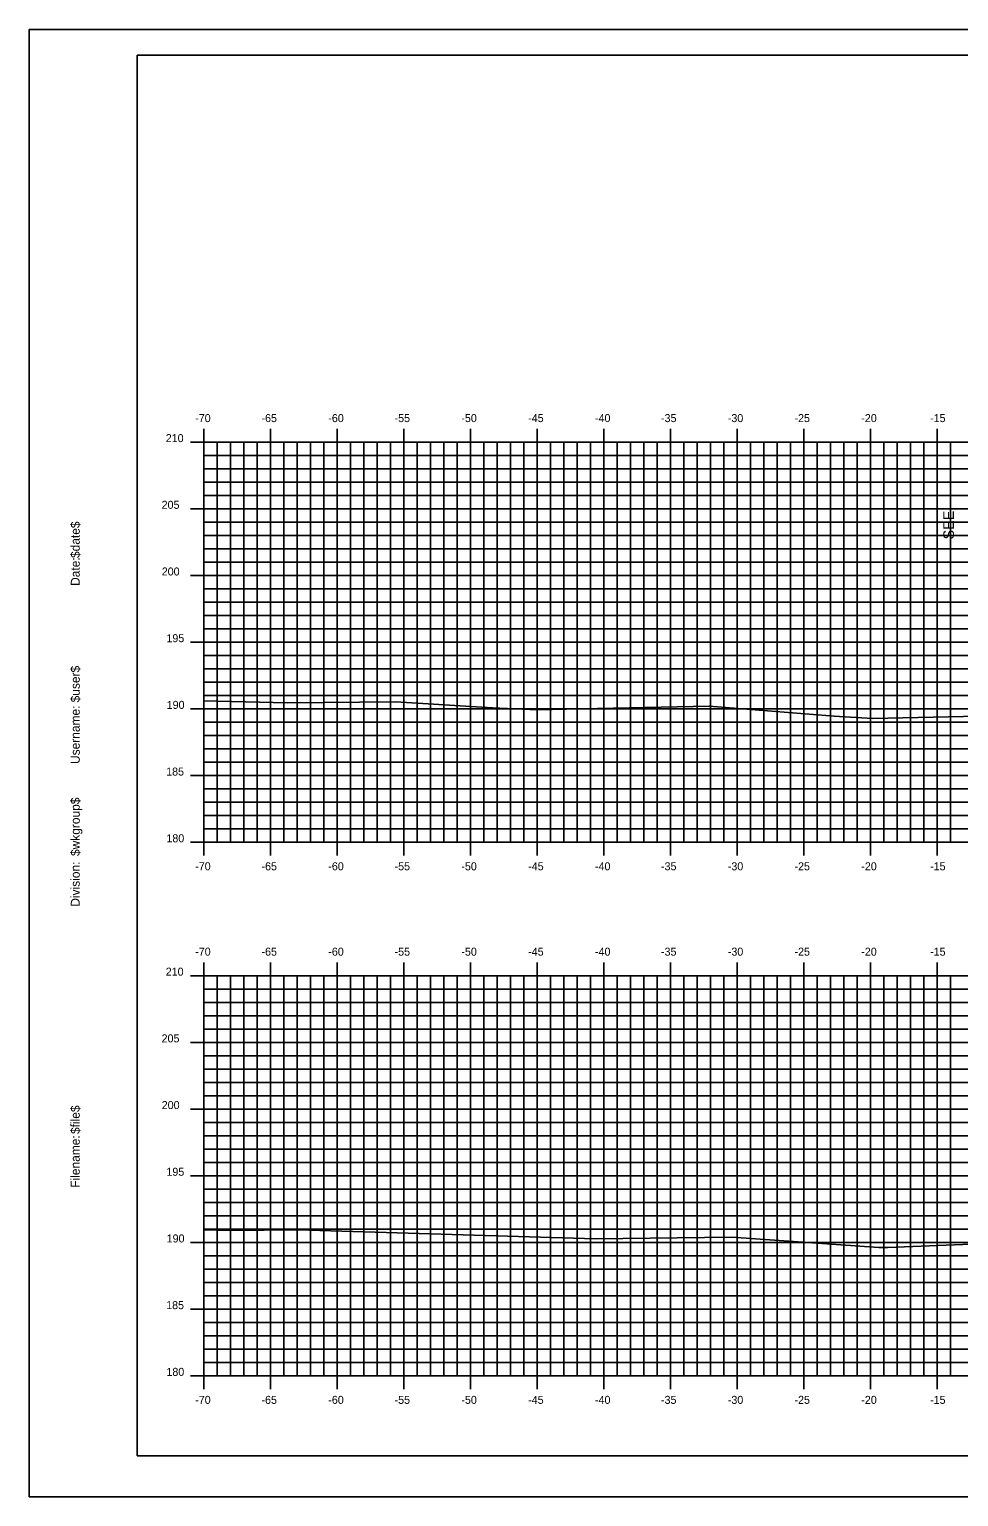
# Model space of a CAD drawing. Extents: x 1723296 to 1723468, y 459560 to 459670.
# Drawn here: x 1723296.1 to 1723365.8, y 459559.6 to 459669.6 of the extents above; entities that cross this region are included whole.
import ezdxf

# ---------------------------------------------------------------- set-up
doc = ezdxf.new("R2010")
doc.units = 0
for name, color, linetype in [('ANNOTATION', 7, 'Continuous'), ('BORDER', 7, 'Continuous'), ('H_V ANNOTATION', 7, 'Continuous'), ('MAJOR', 7, 'Continuous'), ('MINOR', 7, 'Continuous'), ('PLOT BOUNDARY', 7, 'Continuous'), ('S_Roadway_Centerline', 7, 'Continuous')]:
    doc.layers.add(name, color=color, linetype=linetype)

msp = doc.modelspace()

# ---------------------------------------------------------------- linework, layer by layer
at = {"layer": 'BORDER'}
msp.add_lwpolyline([(1723304.2, 459562.61), (1723464.2, 459562.61), (1723464.2, 459667.61), (1723304.2, 459667.61)], close=True, dxfattribs=at)
at = {"layer": 'MAJOR'}
for p, q in [((1723309.2, 459639.61), (1723309.2, 459638.61)), ((1723314.2, 459639.61), (1723314.2, 459638.61)), ((1723319.2, 459639.61), (1723319.2, 459638.61)), ((1723324.2, 459639.61), (1723324.2, 459638.61)), ((1723329.2, 459639.61), (1723329.2, 459638.61)), ((1723334.2, 459639.61), (1723334.2, 459638.61)), ((1723339.2, 459639.61), (1723339.2, 459638.61)), ((1723344.2, 459639.61), (1723344.2, 459638.61)), ((1723349.2, 459639.61), (1723349.2, 459638.61)), ((1723354.2, 459639.61), (1723354.2, 459638.61)), ((1723359.2, 459639.61), (1723359.2, 459638.61)), ((1723364.2, 459639.61), (1723364.2, 459638.61)), ((1723308.2, 459638.61), (1723309.2, 459638.61)), ((1723309.2, 459638.61), (1723449.2, 459638.61)), ((1723309.2, 459608.61), (1723309.2, 459638.61)), ((1723309.2, 459608.61), (1723309.2, 459638.61)), ((1723309.2, 459638.61), (1723449.2, 459638.61)), ((1723314.2, 459608.61), (1723314.2, 459638.61)), ((1723319.2, 459608.61), (1723319.2, 459638.61)), ((1723324.2, 459608.61), (1723324.2, 459638.61)), ((1723329.2, 459608.61), (1723329.2, 459638.61)), ((1723334.2, 459608.61), (1723334.2, 459638.61)), ((1723339.2, 459608.61), (1723339.2, 459638.61)), ((1723344.2, 459608.61), (1723344.2, 459638.61)), ((1723349.2, 459608.61), (1723349.2, 459638.61)), ((1723354.2, 459608.61), (1723354.2, 459638.61)), ((1723359.2, 459608.61), (1723359.2, 459638.61)), ((1723364.2, 459608.61), (1723364.2, 459638.61)), ((1723308.2, 459633.61), (1723309.2, 459633.61)), ((1723309.2, 459633.61), (1723449.2, 459633.61)), ((1723308.2, 459628.61), (1723309.2, 459628.61)), ((1723309.2, 459628.61), (1723449.2, 459628.61)), ((1723308.2, 459623.61), (1723309.2, 459623.61)), ((1723309.2, 459623.61), (1723449.2, 459623.61)), ((1723308.2, 459618.61), (1723309.2, 459618.61)), ((1723309.2, 459618.61), (1723449.2, 459618.61)), ((1723308.2, 459613.61), (1723309.2, 459613.61)), ((1723309.2, 459613.61), (1723449.2, 459613.61)), ((1723308.2, 459608.61), (1723309.2, 459608.61)), ((1723309.2, 459608.61), (1723449.2, 459608.61)), ((1723309.2, 459608.61), (1723449.2, 459608.61)), ((1723309.2, 459607.61), (1723309.2, 459608.61)), ((1723314.2, 459607.61), (1723314.2, 459608.61)), ((1723319.2, 459607.61), (1723319.2, 459608.61)), ((1723324.2, 459607.61), (1723324.2, 459608.61)), ((1723329.2, 459607.61), (1723329.2, 459608.61)), ((1723334.2, 459607.61), (1723334.2, 459608.61)), ((1723339.2, 459607.61), (1723339.2, 459608.61)), ((1723344.2, 459607.61), (1723344.2, 459608.61)), ((1723349.2, 459607.61), (1723349.2, 459608.61)), ((1723354.2, 459607.61), (1723354.2, 459608.61)), ((1723359.2, 459607.61), (1723359.2, 459608.61)), ((1723364.2, 459607.61), (1723364.2, 459608.61)), ((1723309.2, 459599.61), (1723309.2, 459598.61)), ((1723314.2, 459599.61), (1723314.2, 459598.61)), ((1723319.2, 459599.61), (1723319.2, 459598.61)), ((1723324.2, 459599.61), (1723324.2, 459598.61)), ((1723329.2, 459599.61), (1723329.2, 459598.61)), ((1723334.2, 459599.61), (1723334.2, 459598.61)), ((1723339.2, 459599.61), (1723339.2, 459598.61)), ((1723344.2, 459599.61), (1723344.2, 459598.61)), ((1723349.2, 459599.61), (1723349.2, 459598.61)), ((1723354.2, 459599.61), (1723354.2, 459598.61)), ((1723359.2, 459599.61), (1723359.2, 459598.61)), ((1723364.2, 459599.61), (1723364.2, 459598.61)), ((1723308.2, 459598.61), (1723309.2, 459598.61)), ((1723309.2, 459598.61), (1723449.2, 459598.61)), ((1723309.2, 459568.61), (1723309.2, 459598.61)), ((1723309.2, 459568.61), (1723309.2, 459598.61)), ((1723309.2, 459598.61), (1723449.2, 459598.61)), ((1723314.2, 459568.61), (1723314.2, 459598.61)), ((1723319.2, 459568.61), (1723319.2, 459598.61)), ((1723324.2, 459568.61), (1723324.2, 459598.61)), ((1723329.2, 459568.61), (1723329.2, 459598.61)), ((1723334.2, 459568.61), (1723334.2, 459598.61)), ((1723339.2, 459568.61), (1723339.2, 459598.61)), ((1723344.2, 459568.61), (1723344.2, 459598.61)), ((1723349.2, 459568.61), (1723349.2, 459598.61)), ((1723354.2, 459568.61), (1723354.2, 459598.61)), ((1723359.2, 459568.61), (1723359.2, 459598.61)), ((1723364.2, 459568.61), (1723364.2, 459598.61)), ((1723308.2, 459593.61), (1723309.2, 459593.61)), ((1723309.2, 459593.61), (1723449.2, 459593.61)), ((1723308.2, 459588.61), (1723309.2, 459588.61)), ((1723309.2, 459588.61), (1723449.2, 459588.61)), ((1723308.2, 459583.61), (1723309.2, 459583.61)), ((1723309.2, 459583.61), (1723449.2, 459583.61)), ((1723308.2, 459578.61), (1723309.2, 459578.61)), ((1723309.2, 459578.61), (1723449.2, 459578.61)), ((1723308.2, 459573.61), (1723309.2, 459573.61)), ((1723309.2, 459573.61), (1723449.2, 459573.61)), ((1723308.2, 459568.61), (1723309.2, 459568.61)), ((1723309.2, 459568.61), (1723449.2, 459568.61)), ((1723309.2, 459568.61), (1723449.2, 459568.61)), ((1723309.2, 459567.61), (1723309.2, 459568.61)), ((1723314.2, 459567.61), (1723314.2, 459568.61)), ((1723319.2, 459567.61), (1723319.2, 459568.61)), ((1723324.2, 459567.61), (1723324.2, 459568.61)), ((1723329.2, 459567.61), (1723329.2, 459568.61)), ((1723334.2, 459567.61), (1723334.2, 459568.61)), ((1723339.2, 459567.61), (1723339.2, 459568.61)), ((1723344.2, 459567.61), (1723344.2, 459568.61)), ((1723349.2, 459567.61), (1723349.2, 459568.61)), ((1723354.2, 459567.61), (1723354.2, 459568.61)), ((1723359.2, 459567.61), (1723359.2, 459568.61)), ((1723364.2, 459567.61), (1723364.2, 459568.61))]:
    msp.add_line(p, q, dxfattribs=at)
at = {"layer": 'MINOR'}
for p, q in [((1723310.2, 459608.61), (1723310.2, 459638.61)), ((1723311.2, 459608.61), (1723311.2, 459638.61)), ((1723312.2, 459608.61), (1723312.2, 459638.61)), ((1723313.2, 459608.61), (1723313.2, 459638.61)), ((1723315.2, 459608.61), (1723315.2, 459638.61)), ((1723316.2, 459608.61), (1723316.2, 459638.61)), ((1723317.2, 459608.61), (1723317.2, 459638.61)), ((1723318.2, 459608.61), (1723318.2, 459638.61)), ((1723320.2, 459608.61), (1723320.2, 459638.61)), ((1723321.2, 459608.61), (1723321.2, 459638.61)), ((1723322.2, 459608.61), (1723322.2, 459638.61)), ((1723323.2, 459608.61), (1723323.2, 459638.61)), ((1723325.2, 459608.61), (1723325.2, 459638.61)), ((1723326.2, 459608.61), (1723326.2, 459638.61)), ((1723327.2, 459608.61), (1723327.2, 459638.61)), ((1723328.2, 459608.61), (1723328.2, 459638.61)), ((1723330.2, 459608.61), (1723330.2, 459638.61)), ((1723331.2, 459608.61), (1723331.2, 459638.61)), ((1723332.2, 459608.61), (1723332.2, 459638.61)), ((1723333.2, 459608.61), (1723333.2, 459638.61)), ((1723335.2, 459608.61), (1723335.2, 459638.61)), ((1723336.2, 459608.61), (1723336.2, 459638.61)), ((1723337.2, 459608.61), (1723337.2, 459638.61)), ((1723338.2, 459608.61), (1723338.2, 459638.61)), ((1723340.2, 459608.61), (1723340.2, 459638.61)), ((1723341.2, 459608.61), (1723341.2, 459638.61)), ((1723342.2, 459608.61), (1723342.2, 459638.61)), ((1723343.2, 459608.61), (1723343.2, 459638.61)), ((1723345.2, 459608.61), (1723345.2, 459638.61)), ((1723346.2, 459608.61), (1723346.2, 459638.61)), ((1723347.2, 459608.61), (1723347.2, 459638.61)), ((1723348.2, 459608.61), (1723348.2, 459638.61)), ((1723350.2, 459608.61), (1723350.2, 459638.61)), ((1723351.2, 459608.61), (1723351.2, 459638.61)), ((1723352.2, 459608.61), (1723352.2, 459638.61)), ((1723353.2, 459608.61), (1723353.2, 459638.61)), ((1723355.2, 459608.61), (1723355.2, 459638.61)), ((1723356.2, 459608.61), (1723356.2, 459638.61)), ((1723357.2, 459608.61), (1723357.2, 459638.61)), ((1723358.2, 459608.61), (1723358.2, 459638.61)), ((1723360.2, 459608.61), (1723360.2, 459638.61)), ((1723361.2, 459608.61), (1723361.2, 459638.61)), ((1723362.2, 459608.61), (1723362.2, 459638.61)), ((1723363.2, 459608.61), (1723363.2, 459638.61)), ((1723365.2, 459608.61), (1723365.2, 459638.61)), ((1723309.2, 459637.61), (1723449.2, 459637.61)), ((1723309.2, 459637.61), (1723310.21, 459637.61)), ((1723309.2, 459636.61), (1723449.2, 459636.61)), ((1723309.2, 459636.61), (1723310.21, 459636.61)), ((1723309.2, 459635.61), (1723449.2, 459635.61)), ((1723309.2, 459635.61), (1723310.21, 459635.61)), ((1723309.2, 459634.61), (1723449.2, 459634.61)), ((1723309.2, 459634.61), (1723310.21, 459634.61)), ((1723309.2, 459632.61), (1723449.2, 459632.61)), ((1723309.2, 459632.61), (1723310.21, 459632.61)), ((1723309.2, 459631.61), (1723449.2, 459631.61)), ((1723309.2, 459631.61), (1723310.21, 459631.61)), ((1723309.2, 459630.61), (1723449.2, 459630.61)), ((1723309.2, 459630.61), (1723310.21, 459630.61)), ((1723309.2, 459629.61), (1723449.2, 459629.61)), ((1723309.2, 459629.61), (1723310.21, 459629.61)), ((1723309.2, 459627.61), (1723449.2, 459627.61)), ((1723309.2, 459627.61), (1723310.21, 459627.61)), ((1723309.2, 459626.61), (1723449.2, 459626.61)), ((1723309.2, 459626.61), (1723310.21, 459626.61)), ((1723309.2, 459625.61), (1723449.2, 459625.61)), ((1723309.2, 459625.61), (1723310.21, 459625.61)), ((1723309.2, 459624.61), (1723449.2, 459624.61)), ((1723309.2, 459624.61), (1723310.21, 459624.61)), ((1723309.2, 459622.61), (1723449.2, 459622.61)), ((1723309.2, 459622.61), (1723310.21, 459622.61)), ((1723309.2, 459621.61), (1723449.2, 459621.61)), ((1723309.2, 459621.61), (1723310.21, 459621.61)), ((1723309.2, 459620.61), (1723449.2, 459620.61)), ((1723309.2, 459620.61), (1723310.21, 459620.61)), ((1723309.2, 459619.61), (1723449.2, 459619.61)), ((1723309.2, 459619.61), (1723310.21, 459619.61)), ((1723309.2, 459617.61), (1723449.2, 459617.61)), ((1723309.2, 459617.61), (1723310.21, 459617.61)), ((1723309.2, 459616.61), (1723449.2, 459616.61)), ((1723309.2, 459616.61), (1723310.21, 459616.61)), ((1723309.2, 459615.61), (1723449.2, 459615.61)), ((1723309.2, 459615.61), (1723310.21, 459615.61)), ((1723309.2, 459614.61), (1723449.2, 459614.61)), ((1723309.2, 459614.61), (1723310.21, 459614.61)), ((1723309.2, 459612.61), (1723449.2, 459612.61)), ((1723309.2, 459612.61), (1723310.21, 459612.61)), ((1723309.2, 459611.61), (1723449.2, 459611.61)), ((1723309.2, 459611.61), (1723310.21, 459611.61)), ((1723309.2, 459610.61), (1723449.2, 459610.61)), ((1723309.2, 459610.61), (1723310.21, 459610.61)), ((1723309.2, 459609.61), (1723449.2, 459609.61)), ((1723309.2, 459609.61), (1723310.21, 459609.61)), ((1723309.2, 459597.61), (1723449.2, 459597.61)), ((1723309.2, 459597.61), (1723310.21, 459597.61)), ((1723310.2, 459568.61), (1723310.2, 459598.61)), ((1723311.2, 459568.61), (1723311.2, 459598.61)), ((1723312.2, 459568.61), (1723312.2, 459598.61)), ((1723313.2, 459568.61), (1723313.2, 459598.61)), ((1723315.2, 459568.61), (1723315.2, 459598.61)), ((1723316.2, 459568.61), (1723316.2, 459598.61)), ((1723317.2, 459568.61), (1723317.2, 459598.61)), ((1723318.2, 459568.61), (1723318.2, 459598.61)), ((1723320.2, 459568.61), (1723320.2, 459598.61)), ((1723321.2, 459568.61), (1723321.2, 459598.61)), ((1723322.2, 459568.61), (1723322.2, 459598.61)), ((1723323.2, 459568.61), (1723323.2, 459598.61)), ((1723325.2, 459568.61), (1723325.2, 459598.61)), ((1723326.2, 459568.61), (1723326.2, 459598.61)), ((1723327.2, 459568.61), (1723327.2, 459598.61)), ((1723328.2, 459568.61), (1723328.2, 459598.61)), ((1723330.2, 459568.61), (1723330.2, 459598.61)), ((1723331.2, 459568.61), (1723331.2, 459598.61)), ((1723332.2, 459568.61), (1723332.2, 459598.61)), ((1723333.2, 459568.61), (1723333.2, 459598.61)), ((1723335.2, 459568.61), (1723335.2, 459598.61)), ((1723336.2, 459568.61), (1723336.2, 459598.61)), ((1723337.2, 459568.61), (1723337.2, 459598.61)), ((1723338.2, 459568.61), (1723338.2, 459598.61)), ((1723340.2, 459568.61), (1723340.2, 459598.61)), ((1723341.2, 459568.61), (1723341.2, 459598.61)), ((1723342.2, 459568.61), (1723342.2, 459598.61)), ((1723343.2, 459568.61), (1723343.2, 459598.61)), ((1723345.2, 459568.61), (1723345.2, 459598.61)), ((1723346.2, 459568.61), (1723346.2, 459598.61)), ((1723347.2, 459568.61), (1723347.2, 459598.61)), ((1723348.2, 459568.61), (1723348.2, 459598.61)), ((1723350.2, 459568.61), (1723350.2, 459598.61)), ((1723351.2, 459568.61), (1723351.2, 459598.61)), ((1723352.2, 459568.61), (1723352.2, 459598.61)), ((1723353.2, 459568.61), (1723353.2, 459598.61)), ((1723355.2, 459568.61), (1723355.2, 459598.61)), ((1723356.2, 459568.61), (1723356.2, 459598.61)), ((1723357.2, 459568.61), (1723357.2, 459598.61)), ((1723358.2, 459568.61), (1723358.2, 459598.61)), ((1723360.2, 459568.61), (1723360.2, 459598.61)), ((1723361.2, 459568.61), (1723361.2, 459598.61)), ((1723362.2, 459568.61), (1723362.2, 459598.61)), ((1723363.2, 459568.61), (1723363.2, 459598.61)), ((1723365.2, 459568.61), (1723365.2, 459598.61)), ((1723309.2, 459596.61), (1723449.2, 459596.61)), ((1723309.2, 459596.61), (1723310.21, 459596.61)), ((1723309.2, 459595.61), (1723449.2, 459595.61)), ((1723309.2, 459595.61), (1723310.21, 459595.61)), ((1723309.2, 459594.61), (1723449.2, 459594.61)), ((1723309.2, 459594.61), (1723310.21, 459594.61)), ((1723309.2, 459592.61), (1723449.2, 459592.61)), ((1723309.2, 459592.61), (1723310.21, 459592.61)), ((1723309.2, 459591.61), (1723449.2, 459591.61)), ((1723309.2, 459591.61), (1723310.21, 459591.61)), ((1723309.2, 459590.61), (1723449.2, 459590.61)), ((1723309.2, 459590.61), (1723310.21, 459590.61)), ((1723309.2, 459589.61), (1723449.2, 459589.61)), ((1723309.2, 459589.61), (1723310.21, 459589.61)), ((1723309.2, 459587.61), (1723449.2, 459587.61)), ((1723309.2, 459587.61), (1723310.21, 459587.61)), ((1723309.2, 459586.61), (1723449.2, 459586.61)), ((1723309.2, 459586.61), (1723310.21, 459586.61)), ((1723309.2, 459585.61), (1723449.2, 459585.61)), ((1723309.2, 459585.61), (1723310.21, 459585.61)), ((1723309.2, 459584.61), (1723449.2, 459584.61)), ((1723309.2, 459584.61), (1723310.21, 459584.61)), ((1723309.2, 459582.61), (1723449.2, 459582.61)), ((1723309.2, 459582.61), (1723310.21, 459582.61)), ((1723309.2, 459581.61), (1723449.2, 459581.61)), ((1723309.2, 459581.61), (1723310.21, 459581.61)), ((1723309.2, 459580.61), (1723449.2, 459580.61)), ((1723309.2, 459580.61), (1723310.21, 459580.61)), ((1723309.2, 459579.61), (1723449.2, 459579.61)), ((1723309.2, 459579.61), (1723310.21, 459579.61)), ((1723309.2, 459577.61), (1723449.2, 459577.61)), ((1723309.2, 459577.61), (1723310.21, 459577.61)), ((1723309.2, 459576.61), (1723449.2, 459576.61)), ((1723309.2, 459576.61), (1723310.21, 459576.61)), ((1723309.2, 459575.61), (1723449.2, 459575.61)), ((1723309.2, 459575.61), (1723310.21, 459575.61)), ((1723309.2, 459574.61), (1723449.2, 459574.61)), ((1723309.2, 459574.61), (1723310.21, 459574.61)), ((1723309.2, 459572.61), (1723449.2, 459572.61)), ((1723309.2, 459572.61), (1723310.21, 459572.61)), ((1723309.2, 459571.61), (1723449.2, 459571.61)), ((1723309.2, 459571.61), (1723310.21, 459571.61)), ((1723309.2, 459570.61), (1723449.2, 459570.61)), ((1723309.2, 459570.61), (1723310.21, 459570.61)), ((1723309.2, 459569.61), (1723449.2, 459569.61)), ((1723309.2, 459569.61), (1723310.21, 459569.61))]:
    msp.add_line(p, q, dxfattribs=at)
at = {"layer": 'PLOT BOUNDARY'}
msp.add_lwpolyline([(1723296.11, 459559.55), (1723466.11, 459559.55), (1723466.11, 459669.55), (1723296.11, 459669.55)], close=True, dxfattribs=at)
at = {"layer": 'S_Roadway_Centerline'}
for points in [[(1723309.2, 459619.22), (1723315.44, 459619.07), (1723323.59, 459619.13), (1723330.85, 459618.7), (1723334.23, 459618.54), (1723337.49, 459618.62), (1723347.09, 459618.82), (1723356.46, 459618.06), (1723359.35, 459617.9), (1723369.59, 459618.12), (1723379.96, 459617.79), (1723384.01, 459617.61), (1723402.73, 459617.01), (1723408.94, 459616.86), (1723416.53, 459616.84), (1723423.26, 459616.81), (1723428.32, 459616.72), (1723433.19, 459616.5), (1723445.78, 459616.14), (1723449.2, 459616.14)], [(1723309.2, 459579.55), (1723311.22, 459579.51), (1723316.24, 459579.55), (1723335.26, 459578.97), (1723338.56, 459578.89), (1723348.8, 459579), (1723359.81, 459578.24), (1723360.1, 459578.23), (1723360.49, 459578.24), (1723371.74, 459578.69), (1723380.82, 459577.97), (1723387.77, 459577.74), (1723402.29, 459577.58), (1723406.73, 459577.43), (1723411.68, 459577.24), (1723425.33, 459576.89), (1723437.59, 459576.84), (1723445.67, 459576.71), (1723449.2, 459576.66)]]:
    msp.add_lwpolyline(points, dxfattribs=at)

# ---------------------------------------------------------------- texts
at = {"layer": 'ANNOTATION'}
msp.add_text('SEE', height=0.8, rotation=90, dxfattribs=at).set_placement((1723365.45, 459631.32))
at = {"layer": 'BORDER'}
for s, p in [('$date$', (1723299.89, 459629.92)), ('Date:', (1723299.89, 459627.83)), ('$user$', (1723299.89, 459619.1)), ('Username:', (1723299.89, 459614.48)), ('$wkgroup$', (1723299.89, 459607.58)), ('Division:', (1723299.89, 459603.78)), ('$file$', (1723299.89, 459586.74)), ('Filename:', (1723299.89, 459582.71))]:
    msp.add_text(s, height=0.67, rotation=90, dxfattribs=at).set_placement(p)
at = {"layer": 'H_V ANNOTATION'}
for s, p in [('-70', (1723308.55, 459640.11)), ('-65', (1723313.52, 459640.11)), ('-60', (1723318.53, 459640.11)), ('-55', (1723323.5, 459640.11)), ('-50', (1723328.51, 459640.11)), ('-45', (1723333.52, 459640.11)), ('-40', (1723338.53, 459640.11)), ('-35', (1723343.48, 459640.11)), ('-30', (1723348.49, 459640.11)), ('-25', (1723353.49, 459640.11)), ('-20', (1723358.5, 459640.11)), ('-15', (1723363.66, 459640.11)), ('210', (1723306.34, 459638.61)), ('205', (1723306.03, 459633.61)), ('200', (1723306.04, 459628.61)), ('195', (1723306.39, 459623.61)), ('190', (1723306.41, 459618.61)), ('185', (1723306.37, 459613.61)), ('180', (1723306.39, 459608.61)), ('-70', (1723308.55, 459606.51)), ('-65', (1723313.52, 459606.51)), ('-60', (1723318.53, 459606.51)), ('-55', (1723323.5, 459606.51)), ('-50', (1723328.51, 459606.51)), ('-45', (1723333.52, 459606.51)), ('-40', (1723338.53, 459606.51)), ('-35', (1723343.48, 459606.51)), ('-30', (1723348.49, 459606.51)), ('-25', (1723353.49, 459606.51)), ('-20', (1723358.5, 459606.51)), ('-15', (1723363.66, 459606.51)), ('-70', (1723308.55, 459600.11)), ('-65', (1723313.52, 459600.11)), ('-60', (1723318.53, 459600.11)), ('-55', (1723323.5, 459600.11)), ('-50', (1723328.51, 459600.11)), ('-45', (1723333.52, 459600.11)), ('-40', (1723338.53, 459600.11)), ('-35', (1723343.48, 459600.11)), ('-30', (1723348.49, 459600.11)), ('-25', (1723353.49, 459600.11)), ('-20', (1723358.5, 459600.11)), ('-15', (1723363.66, 459600.11)), ('210', (1723306.34, 459598.61)), ('205', (1723306.03, 459593.61)), ('200', (1723306.04, 459588.61)), ('195', (1723306.39, 459583.61)), ('190', (1723306.41, 459578.61)), ('185', (1723306.37, 459573.61)), ('180', (1723306.39, 459568.61)), ('-70', (1723308.55, 459566.51)), ('-65', (1723313.52, 459566.51)), ('-60', (1723318.53, 459566.51)), ('-55', (1723323.5, 459566.51)), ('-50', (1723328.51, 459566.51)), ('-45', (1723333.52, 459566.51)), ('-40', (1723338.53, 459566.51)), ('-35', (1723343.48, 459566.51)), ('-30', (1723348.49, 459566.51)), ('-25', (1723353.49, 459566.51)), ('-20', (1723358.5, 459566.51)), ('-15', (1723363.66, 459566.51))]:
    msp.add_text(s, height=0.6, dxfattribs=at).set_placement(p)
at = {"layer": 'MAJOR'}
for p in [(1723309.2, 459608.61), (1723309.2, 459568.61)]:
    msp.add_text('-', height=0.006, dxfattribs=at).set_placement(p)

doc.saveas('drawing.dxf')
